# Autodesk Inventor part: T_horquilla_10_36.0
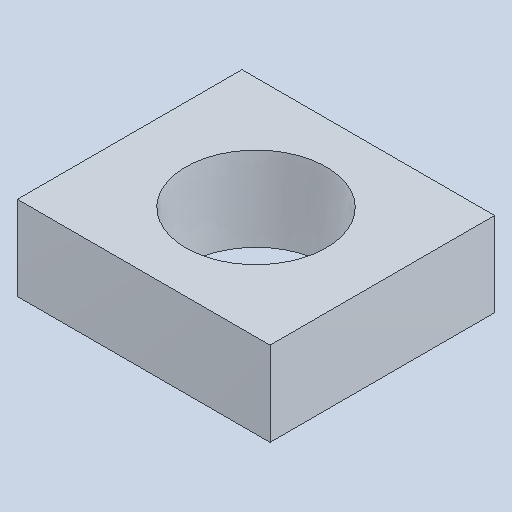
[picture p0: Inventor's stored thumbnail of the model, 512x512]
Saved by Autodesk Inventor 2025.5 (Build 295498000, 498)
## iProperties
Created: 2026-10
Part Number: T_horquilla_10_36.0
Material: Genérico
Document SubType Name: Modeling
Designer: Luis M
Density: 1 g/cm^3
Appearance: Valor por defecto
Author: Luis M
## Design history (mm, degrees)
feature "Base1"
node "Sólido1"
